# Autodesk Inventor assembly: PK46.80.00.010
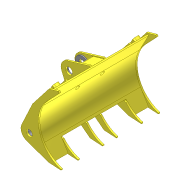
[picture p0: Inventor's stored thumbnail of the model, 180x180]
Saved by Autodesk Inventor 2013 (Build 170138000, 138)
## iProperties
Shininess: 64.0
Length Units: 11269
Angle Units: 11279
Time Units: 11290
Mass Units: 11283
Length Display Precision: 3
Angle Display Precision: 2
Compacted: True
Created: 2005-01
Part Number: PK46.80.00.010
Document SubType Name: Assembly
Designer: SAlex
Manufacturer: Standard
Standards Organization: Custom
Density: 0.0
Volumn: 0.0
Area: 0.0
PropertySet Name: Model Information
Control State: 0
Master: False
Checked Out: False
Checked Out Date: 2008-10-15
Last Check In Date: 2008-10-15
Author: SAlex
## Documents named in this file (9)
- C:\Product Design Suite 2013 Test Drive\Dynamic Simulation\Workspace\Assy, Chassis, Front\PK46.80.00.010.iam
- C:\Product Design Suite 2013 Test Drive\Dynamic Simulation\Workspace\Assy, Chassis, Front\PK46.80.00.012.ipt
- C:\Product Design Suite 2013 Test Drive\Dynamic Simulation\Workspace\Assy, Chassis, Front\PK46.80.00.022.ipt
- C:\Product Design Suite 2013 Test Drive\Dynamic Simulation\Workspace\Assy, Chassis, Front\PK46.80.00.015.ipt
- C:\Product Design Suite 2013 Test Drive\Dynamic Simulation\Workspace\Assy, Chassis, Front\PK46.80.00.028.ipt
- C:\Product Design Suite 2013 Test Drive\Dynamic Simulation\Workspace\Assy, Chassis, Front\PK46.25.02.003.ipt
- C:\Product Design Suite 2013 Test Drive\Dynamic Simulation\Workspace\Assy, Chassis, Front\PK46.80.00.035.ipt
- C:\Product Design Suite 2013 Test Drive\Dynamic Simulation\Workspace\Assy, Chassis, Front\PK46.80.00.034.ipt
- C:\Product Design Suite 2013 Test Drive\Dynamic Simulation\Workspace\Assy, Chassis, Front\PK46.80.00.032.ipt
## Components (16 placed, 8 different names)
1. PK46.80.00.032:1 — Совмещение:3, Совмещение:5, Угол:1, Совмещение:24, Совмещение:25, Совмещение:26, Заподлицо:24, Совмещение:33, Совмещение:38, Совмещение:39, Mate:40, Mate:41, Mate:42
2. PK46.80.00.012:1 — Заподлицо:21, Совмещение:21, Вставка:11, Совмещение:22, Заподлицо:22, Совмещение:10, Совмещение:36, Совмещение:37, Совмещение:38
3. PK46.80.00.012:2 — Заподлицо:21, Вставка:10, Совмещение:23, Совмещение:37, Заподлицо:27
4. PK46.25.02.003:1 — Вставка:10
5. PK46.25.02.003:2 — Вставка:11
6. PK46.80.00.034:2 — Вставка:7, Заподлицо:3, Совмещение:28, Совмещение:29, Совмещение:31, Mate:41, Flush:28
7. PK46.80.00.035:2 — Вставка:6, Заподлицо:3, Совмещение:21, Совмещение:29, Совмещение:31
8. PK46.80.00.035:1 — Вставка:4, Заподлицо:2, Совмещение:30, Совмещение:32
9. PK46.80.00.034:1 — Вставка:5, Заподлицо:2, Совмещение:3, Совмещение:27, Совмещение:30, Совмещение:32, Mate:40, Mate:42, Flush:28
10. PK46.80.00.015:1 — Вставка:7, Совмещение:4, Заподлицо:26
11. PK46.80.00.015:2 — Вставка:6
12. PK46.80.00.015:3 — Вставка:4
13. PK46.80.00.015:4 — Вставка:5, Совмещение:4, Совмещение:7, Заподлицо:25
14. PK46.80.00.022:1 — Совмещение:22, Совмещение:23, Заподлицо:22, Совмещение:24, Заподлицо:27
15. PK46.80.00.028:1 — Совмещение:25, Совмещение:27, Заподлицо:23, Заподлицо:24
16. PK46.80.00.028:2 — Совмещение:26, Заподлицо:23, Совмещение:28
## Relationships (42: Mate 25, Flush 10, Insert 6, Angle 1)
- Вставка:4 [Insert]: PK46.80.00.035:1 ↔ PK46.80.00.015:3
- Вставка:5 [Insert]: PK46.80.00.034:1 ↔ PK46.80.00.015:4
- Вставка:6 [Insert]: PK46.80.00.035:2 ↔ PK46.80.00.015:2
- Вставка:7 [Insert]: PK46.80.00.034:2 ↔ PK46.80.00.015:1
- Заподлицо:2 [Flush]: PK46.80.00.035:1 ↔ PK46.80.00.034:1
- Заподлицо:3 [Flush]: PK46.80.00.034:2 ↔ PK46.80.00.035:2
- Совмещение:3 [Mate]: PK46.80.00.032:1 ↔ PK46.80.00.034:1
- Совмещение:4 [Mate]: PK46.80.00.015:1 ↔ PK46.80.00.015:4
- Совмещение:5 [Mate]: PK46.80.00.032:1
- Совмещение:7 [Mate]: PK46.80.00.015:4
- Угол:1 [Angle]: PK46.80.00.032:1
- Заподлицо:21 [Flush]: PK46.80.00.012:1 ↔ PK46.80.00.012:2
- Совмещение:21 [Mate]: PK46.80.00.012:1 ↔ PK46.80.00.035:2
- Вставка:10 [Insert]: PK46.80.00.012:2 ↔ PK46.25.02.003:1
- Вставка:11 [Insert]: PK46.80.00.012:1 ↔ PK46.25.02.003:2
- Совмещение:22 [Mate]: PK46.80.00.012:1 ↔ PK46.80.00.022:1
- Совмещение:23 [Mate]: PK46.80.00.012:2 ↔ PK46.80.00.022:1
- Заподлицо:22 [Flush]: PK46.80.00.012:1 ↔ PK46.80.00.022:1
- Совмещение:24 [Mate]: PK46.80.00.032:1 ↔ PK46.80.00.022:1
- Совмещение:25 [Mate]: PK46.80.00.032:1 ↔ PK46.80.00.028:1
- Совмещение:26 [Mate]: PK46.80.00.032:1 ↔ PK46.80.00.028:2
- Совмещение:27 [Mate]: PK46.80.00.034:1 ↔ PK46.80.00.028:1
- Заподлицо:23 [Flush]: PK46.80.00.028:1 ↔ PK46.80.00.028:2
- Совмещение:28 [Mate]: PK46.80.00.034:2 ↔ PK46.80.00.028:2
- Заподлицо:24 [Flush]: PK46.80.00.032:1 ↔ PK46.80.00.028:1
- Совмещение:29 [Mate]: PK46.80.00.034:2 ↔ PK46.80.00.035:2
- Совмещение:30 [Mate]: PK46.80.00.035:1 ↔ PK46.80.00.034:1
- Совмещение:31 [Mate]: PK46.80.00.034:2 ↔ PK46.80.00.035:2
- Совмещение:32 [Mate]: PK46.80.00.035:1 ↔ PK46.80.00.034:1
- Заподлицо:25 [Flush]: PK46.80.00.015:4
- Заподлицо:26 [Flush]: PK46.80.00.015:1
- Совмещение:33 [Mate]: PK46.80.00.032:1
- Совмещение:10 [Mate]: PK46.80.00.012:1
- Совмещение:36 [Mate]: PK46.80.00.012:1
- Совмещение:37 [Mate]: PK46.80.00.012:1 ↔ PK46.80.00.012:2
- Совмещение:38 [Mate]: PK46.80.00.032:1 ↔ PK46.80.00.012:1
- Заподлицо:27 [Flush]: PK46.80.00.012:2 ↔ PK46.80.00.022:1
- Совмещение:39 [Mate]: PK46.80.00.032:1
- Mate:40: PK46.80.00.032:1 ↔ PK46.80.00.034:1
- Mate:41: PK46.80.00.032:1 ↔ PK46.80.00.034:2
- Mate:42: PK46.80.00.032:1 ↔ PK46.80.00.034:1
- Flush:28: PK46.80.00.034:2 ↔ PK46.80.00.034:1
